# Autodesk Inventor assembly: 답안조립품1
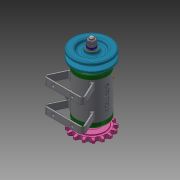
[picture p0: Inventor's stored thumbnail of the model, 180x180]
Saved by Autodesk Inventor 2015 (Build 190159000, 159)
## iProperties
Created: 2021-12
Part Number: 답안조립품1
Document SubType Name: Assembly
Designer: pc-04
Author: pc-04
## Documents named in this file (16)
- C:\Users\pc-04\Desktop\711206V1020.zip\답안조립품1.iam
- C:\Users\pc-04\Desktop\711206V1020.zip\본체.ipt
- C:\Users\pc-04\Desktop\711206V1020.zip\니플 M6 x 0.75.ipt
- C:\Users\pc-04\Desktop\711206V1020.zip\베어링 6002.ipt
- C:\Users\pc-04\Desktop\711206V1020.zip\커버.ipt
- C:\Users\pc-04\Desktop\711206V1020.zip\오일 실 15 x 25 x 7.ipt
- C:\Users\pc-04\Desktop\711206V1020.zip\볼트 M4 x 12.ipt
- C:\Users\pc-04\Desktop\711206V1020.zip\축.ipt
- C:\Users\pc-04\Desktop\711206V1020.zip\V벨트풀리.ipt
- C:\Users\pc-04\Desktop\711206V1020.zip\스프로킷.ipt
- C:\Users\pc-04\Desktop\711206V1020.zip\키 3 x 3.ipt
- C:\Users\pc-04\Desktop\711206V1020.zip\와셔 8 x 17.ipt
- C:\Users\pc-04\Desktop\711206V1020.zip\스프링와셔 8.ipt
- C:\Users\pc-04\Desktop\711206V1020.zip\너트 M8.ipt
- C:\Users\pc-04\Desktop\711206V1020.zip\와셔 6 x 11.5.ipt
- C:\Users\pc-04\Desktop\711206V1020.zip\볼트 M6 x 8.ipt
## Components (11 placed, 3 different names)
1. KS B 2023 6002 - 15 x 32 x 9:1
2. KS B 2023 6002 - 15 x 32 x 9:2
3. ISO 4762 M4 x 12:1
4. ISO 4762 M4 x 12:2
5. ISO 4762 M4 x 12:3
6. ISO 4762 M4 x 12:4
7. ISO 4762 M4 x 12:5
8. ISO 4762 M4 x 12:6
9. ISO 4762 M4 x 12:7
10. ISO 4762 M4 x 12:8
11. V벨트풀리:1
